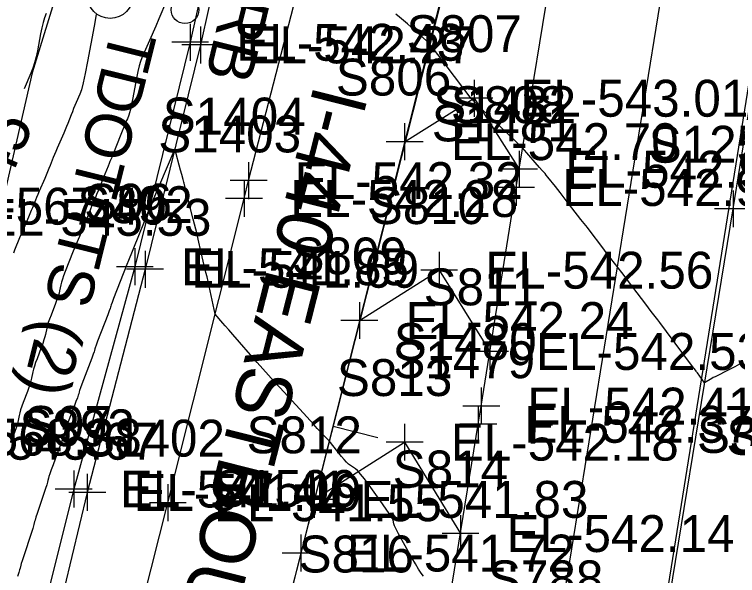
# Model space of a CAD drawing. Extents: x 1724534 to 1727318, y 657156 to 660047.
# Drawn here: x 1725578 to 1725656.3, y 659554.5 to 659615.3 of the extents above; entities that cross this region are included whole.
import ezdxf

# ---------------------------------------------------------------- set-up
doc = ezdxf.new("R2010")
doc.units = 0
for name, color, linetype in [('SURVEY - CENTERLINE - Preliminary', 7, 'Continuous'), ('SURVEY - CENTERLINE - Preliminary Text', 7, 'Continuous'), ('SURVEY - CONTOURS - Index with Text', 7, 'Continuous'), ('SURVEY - CONTOURS - Intermediate with optional Text', 7, 'Continuous'), ('SURVEY - DRAINAGE - Area Shapes', 7, 'Continuous'), ('SURVEY - DTM - Breaklines', 7, 'Continuous'), ('SURVEY - DTM - Breaklines - Points - Elevations', 7, 'Continuous'), ('SURVEY - DTM - Breaklines - Points - Locators', 7, 'Continuous'), ('SURVEY - DTM - Breaklines - Points - Numbers', 7, 'Continuous'), ('SURVEY - NON-TRANSPORTATION - Features - Points - Elevations', 7, 'Continuous'), ('SURVEY - TRAFFIC CONTROL - Pavement Marking - Points - Elevations', 7, 'Continuous'), ('SURVEY - TRAFFIC CONTROL - Pavement Marking - Points - Locators', 7, 'Continuous'), ('SURVEY - TRAFFIC CONTROL - Pavement Marking - Points - Numbers', 7, 'Continuous'), ('SURVEY - TRAFFIC CONTROL - Pavement Marking with Text', 7, 'Continuous'), ('SURVEY - TRANSPORTATION - Features', 7, 'Continuous'), ('SURVEY - TRANSPORTATION - Features - Points - Elevations', 7, 'Continuous'), ('SURVEY - TRANSPORTATION - Features - Points - Locators', 7, 'Continuous'), ('SURVEY - TRANSPORTATION - Features - Points - Numbers', 7, 'Continuous'), ('SURVEY - TRANSPORTATION - Features Text', 7, 'Continuous'), ('SURVEY - TRANSPORTATION - Roads', 7, 'Continuous'), ('SURVEY - TRANSPORTATION - Roads - Points - Elevations', 7, 'Continuous'), ('SURVEY - TRANSPORTATION - Roads - Points - Locators', 7, 'Continuous'), ('SURVEY - TRANSPORTATION - Roads - Points - Numbers', 7, 'Continuous'), ('SURVEY - TRANSPORTATION - Roads Text', 7, 'Continuous'), ('SURVEY - UTILITIES - Electric (Lighting) with Text', 7, 'Continuous'), ('SURVEY - UTILITIES - Fiber Optic Cable (Underground) with Text', 7, 'Continuous'), ('SURVEY - UTILITIES - Poles and Miscellaneous with Text', 7, 'Continuous')]:
    doc.layers.add(name, color=color, linetype=linetype)

msp = doc.modelspace()

# ---------------------------------------------------------------- linework, layer by layer
at = {"layer": 'SURVEY - CENTERLINE - Preliminary'}
msp.add_line((1725628.749, 659634.745), (1725510.016, 659165.778), dxfattribs=at)
msp.add_line((1725628.749, 659634.745), (1725510.016, 659165.778), dxfattribs=at)
msp.add_line((1725628.749, 659634.745), (1725510.016, 659165.778), dxfattribs=at)
at = {"layer": 'SURVEY - CENTERLINE - Preliminary Text'}
msp.add_line((1725612.522, 659570.651), (1725617.369, 659569.424), dxfattribs=at)
at = {"layer": 'SURVEY - CONTOURS - Index with Text'}
msp.add_lwpolyline([(1725581.44, 659615.386), (1725581.278, 659614.944), (1725581.126, 659614.432), (1725580.983, 659613.849), (1725580.851, 659613.197), (1725580.51, 659611.362), (1725580.37, 659610.695), (1725580.204, 659610.068), (1725580.014, 659609.482), (1725579.799, 659608.938), (1725579.065, 659607.246)], dxfattribs=at)
at = {"layer": 'SURVEY - CONTOURS - Intermediate with optional Text'}
for points in [[(1725594.473, 659616.778), (1725593.644, 659614.818), (1725593.31, 659614.042), (1725591.795, 659610.582), (1725591.659, 659610.216), (1725591.52, 659609.728), (1725591.378, 659609.118), (1725591.233, 659608.387), (1725590.84, 659606.274), (1725590.703, 659605.562), (1725590.587, 659605.011), (1725590.491, 659604.62), (1725590.416, 659604.39), (1725590.242, 659603.991), (1725590.159, 659603.794), (1725590.04, 659603.501), (1725589.691, 659602.629), (1725588.936, 659600.727), (1725588.776, 659600.331), (1725588.651, 659600.025), (1725588.56, 659599.809), (1725588.362, 659599.354), (1725588.271, 659599.141), (1725588.149, 659598.843), (1725587.807, 659597.993), (1725587.078, 659596.163), (1725586.92, 659595.772), (1725586.792, 659595.461), (1725586.694, 659595.23), (1725586.471, 659594.72), (1725586.373, 659594.492), (1725586.248, 659594.189), (1725585.914, 659593.359), (1725585.211, 659591.601), (1725585.054, 659591.215), (1725584.923, 659590.9), (1725584.818, 659590.653), (1725584.374, 659589.636), (1725583.508, 659587.417), (1725583.34, 659586.974), (1725583.206, 659586.589), (1725583.107, 659586.262), (1725583.041, 659585.994), (1725582.91, 659585.356), (1725582.845, 659585.089), (1725582.748, 659584.766), (1725582.617, 659584.386), (1725582.454, 659583.95), (1725581.977, 659582.713), (1725581.814, 659582.275), (1725581.682, 659581.891), (1725581.583, 659581.56), (1725581.515, 659581.283), (1725581.378, 659580.613), (1725581.311, 659580.337), (1725581.213, 659580.009), (1725581.085, 659579.63), (1725580.926, 659579.199), (1725580.462, 659577.983), (1725580.303, 659577.552), (1725580.174, 659577.169), (1725580.075, 659576.836), (1725580.006, 659576.552), (1725579.863, 659575.859), (1725579.795, 659575.576), (1725579.698, 659575.245), (1725579.572, 659574.868), (1725579.417, 659574.443), (1725578.965, 659573.247), (1725578.81, 659572.821), (1725578.683, 659572.44), (1725578.585, 659572.105), (1725578.515, 659571.814), (1725578.366, 659571.099), (1725578.297, 659570.81), (1725578.2, 659570.477), (1725578.076, 659570.101), (1725577.925, 659569.682)], [(1725586.882, 659615.305), (1725586.645, 659614.04), (1725585.934, 659610.21), (1725585.682, 659608.911), (1725585.46, 659607.887), (1725585.269, 659607.138), (1725585.107, 659606.664), (1725584.717, 659605.765), (1725584.572, 659605.427), (1725584.429, 659605.088), (1725584.29, 659604.748), (1725584.152, 659604.405), (1725583.79, 659603.491), (1725583.651, 659603.146), (1725583.508, 659602.798), (1725583.36, 659602.446), (1725583.207, 659602.091), (1725582.792, 659601.139), (1725582.64, 659600.787), (1725582.495, 659600.443), (1725582.357, 659600.107), (1725582.225, 659599.78), (1725581.882, 659598.919), (1725581.749, 659598.589), (1725581.607, 659598.246), (1725581.457, 659597.89), (1725581.297, 659597.52), (1725580.7, 659596.148), (1725580.552, 659595.799), (1725580.414, 659595.469), (1725580.288, 659595.157), (1725579.966, 659594.349), (1725579.838, 659594.034), (1725579.698, 659593.696), (1725579.544, 659593.335), (1725578.915, 659591.894), (1725578.562, 659591.085), (1725578.038, 659589.743), (1725577.929, 659589.438)], [(1725656.549, 659577.375), (1725656.023, 659577.1), (1725655.58, 659576.871), (1725655.222, 659576.688), (1725654.946, 659576.551), (1725654.323, 659576.248), (1725654.099, 659576.137), (1725653.891, 659576.03), (1725653.7, 659575.927), (1725653.527, 659575.829), (1725652.757, 659575.383), (1725651.976, 659576.44), (1725651.908, 659576.535), (1725651.893, 659576.564), (1725651.835, 659576.638), (1725651.757, 659576.733), (1725651.439, 659577.154), (1725648.634, 659580.917), (1725647.902, 659581.891), (1725647.674, 659582.19), (1725646.977, 659583.096), (1725646.387, 659583.876), (1725644.523, 659586.359), (1725644.142, 659586.861), (1725643.779, 659587.336), (1725642.209, 659589.363), (1725641.61, 659590.144), (1725640.365, 659591.789), (1725640.06, 659592.187), (1725639.364, 659593.083), (1725637.752, 659595.148), (1725637.437, 659595.557), (1725637.108, 659595.988), (1725636.592, 659596.649), (1725635.787, 659597.672), (1725635.616, 659597.884), (1725635.48, 659598.047), (1725635.38, 659598.161), (1725635.16, 659598.399), (1725634.889, 659598.702), (1725634.409, 659599.253), (1725633.04, 659600.827), (1725629.195, 659604.496), (1725628.716, 659604.957), (1725628.38, 659605.286), (1725628.185, 659605.482), (1725627.745, 659605.945), (1725627.663, 659606.029), (1725627.608, 659606.083), (1725627.58, 659606.105), (1725627.543, 659606.124), (1725627.525, 659606.138), (1725627.5, 659606.165), (1725627.466, 659606.205), (1725622.953, 659612.149), (1725620.991, 659613.91), (1725620.571, 659614.281), (1725620.152, 659614.641), (1725619.733, 659614.99), (1725619.315, 659615.327)], [(1725622.31, 659554.396), (1725622.066, 659554.733), (1725621.775, 659555.18), (1725621.438, 659555.74), (1725621.055, 659556.41), (1725619.97, 659558.348), (1725619.61, 659559.002), (1725619.345, 659559.509), (1725619.175, 659559.87), (1725619.099, 659560.084), (1725619.022, 659560.462), (1725618.928, 659560.681), (1725618.706, 659561.053), (1725618.354, 659561.58), (1725617.873, 659562.261), (1725616.417, 659564.281), (1725615.915, 659564.96), (1725615.501, 659565.482), (1725615.174, 659565.847), (1725614.936, 659566.056), (1725614.416, 659566.401), (1725614.209, 659566.56), (1725613.978, 659566.776), (1725613.723, 659567.05), (1725613.444, 659567.381), (1725612.086, 659569.062), (1725610.805, 659570.428), (1725610.429, 659570.837), (1725609.67, 659571.682), (1725608.917, 659572.505), (1725606.758, 659574.853), (1725606.151, 659575.517), (1725605.541, 659576.193), (1725604.928, 659576.882), (1725604.31, 659577.583), (1725601.679, 659580.588), (1725601.218, 659581.11), (1725600.84, 659581.53), (1725600.589, 659581.818), (1725599.743, 659582.803), (1725598.876, 659586.848), (1725598.756, 659587.322), (1725598.598, 659587.949), (1725598.531, 659588.222), (1725598.448, 659588.572), (1725598.237, 659589.499), (1725597.913, 659590.939), (1725597.788, 659591.48), (1725597.658, 659592.025), (1725597.521, 659592.572), (1725597.379, 659593.123), (1725596.859, 659595.101), (1725596.668, 659595.844), (1725596.611, 659596.081), (1725596.387, 659597.024), (1725596.367, 659597.104), (1725596.291, 659597.396), (1725596.137, 659597.96), (1725596.015, 659598.405), (1725595.375, 659600.736), (1725593.601, 659596.567), (1725592.599, 659594.22), (1725592.047, 659592.835), (1725590.302, 659588.464), (1725590.258, 659588.356), (1725590.186, 659588.187), (1725588.751, 659584.509), (1725588.586, 659584.079), (1725588.484, 659583.803), (1725588.444, 659583.681), (1725588.419, 659583.558), (1725588.379, 659583.437), (1725588.28, 659583.166), (1725588.121, 659582.746), (1725587.018, 659579.881), (1725586.857, 659579.455), (1725586.756, 659579.174), (1725586.714, 659579.039), (1725586.68, 659578.875), (1725586.638, 659578.742), (1725586.54, 659578.466), (1725586.384, 659578.048), (1725585.315, 659575.237), (1725585.158, 659574.814), (1725585.058, 659574.529), (1725585.014, 659574.384), (1725584.972, 659574.181), (1725584.929, 659574.037), (1725584.831, 659573.757), (1725584.679, 659573.341), (1725584.472, 659572.789), (1725583.847, 659571.136), (1725583.64, 659570.582), (1725583.487, 659570.161), (1725583.387, 659569.873), (1725583.342, 659569.717), (1725583.292, 659569.479), (1725583.247, 659569.325), (1725583.151, 659569.041), (1725583.002, 659568.628), (1725582.801, 659568.085), (1725582.195, 659566.466), (1725581.994, 659565.922), (1725581.844, 659565.504), (1725581.745, 659565.213), (1725581.698, 659565.047), (1725581.641, 659564.775), (1725581.598, 659564.61), (1725581.509, 659564.32), (1725581.376, 659563.904), (1725581.197, 659563.363), (1725580.483, 659561.208), (1725580.347, 659560.789), (1725580.255, 659560.493), (1725580.205, 659560.321), (1725580.131, 659560.026), (1725580.081, 659559.855), (1725579.99, 659559.563), (1725579.857, 659559.15), (1725578.982, 659556.497), (1725578.848, 659556.08), (1725578.755, 659555.781), (1725578.703, 659555.6), (1725578.621, 659555.275), (1725578.57, 659555.095), (1725578.479, 659554.8), (1725578.347, 659554.389)]]:
    msp.add_lwpolyline(points, dxfattribs=at)
at = {"layer": 'SURVEY - DRAINAGE - Area Shapes'}
msp.add_lwpolyline([(1725457.865, 659006.777), (1725413.857, 659016.262), (1725297.605, 659050.843), (1725314.042, 659296.608), (1725386.76, 659493.901), (1725483.401, 659755.229), (1725623.949, 659732.704), (1725676.22, 659724.326), (1725634.82, 659466.017), (1725543.324, 659353.721), (1725499.683, 659185.923), (1725479.088, 659106.738)], close=True, dxfattribs=at)
at = {"layer": 'SURVEY - DTM - Breaklines'}
msp.add_lwpolyline([(1725602.477, 659636.589), (1725597.046, 659612.281), (1725591.056, 659587.95), (1725584.432, 659563.857), (1725578.377, 659539.615), (1725572.193, 659515.421), (1725566.455, 659491.037), (1725562.449, 659475.306), (1725561.076, 659469.841), (1725554.596, 659445.712), (1725548.416, 659421.487), (1725542.14, 659397.279), (1725535.913, 659373.067), (1725529.984, 659349.877), (1725523.806, 659325.59), (1725517.787, 659301.313), (1725511.183, 659275.168), (1725504.884, 659250.966), (1725498.725, 659226.793)], dxfattribs=at)
at = {"layer": 'SURVEY - DTM - Breaklines - Points - Locators'}
for p, q in [((1725597.046, 659614.281), (1725597.046, 659610.281)), ((1725599.046, 659612.281), (1725595.046, 659612.281)), ((1725591.056, 659589.95), (1725591.056, 659585.95)), ((1725593.056, 659587.95), (1725589.056, 659587.95)), ((1725584.432, 659565.857), (1725584.432, 659561.857)), ((1725586.432, 659563.857), (1725582.432, 659563.857))]:
    msp.add_line(p, q, dxfattribs=at)
at = {"layer": 'SURVEY - TRAFFIC CONTROL - Pavement Marking - Points - Locators'}
for p, q in [((1725627.806, 659608.215), (1725627.806, 659604.215)), ((1725629.806, 659606.215), (1725625.806, 659606.215)), ((1725620.269, 659603.507), (1725620.269, 659599.507)), ((1725622.269, 659601.507), (1725618.269, 659601.507)), ((1725632.661, 659600.515), (1725632.661, 659596.515)), ((1725634.661, 659598.515), (1725630.661, 659598.515)), ((1725624.011, 659589.575), (1725624.011, 659585.575)), ((1725626.011, 659587.575), (1725622.011, 659587.575)), ((1725615.379, 659584.118), (1725615.379, 659580.118)), ((1725617.379, 659582.118), (1725613.379, 659582.118)), ((1725629.508, 659580.767), (1725629.508, 659576.767)), ((1725631.508, 659578.767), (1725627.508, 659578.767)), ((1725620.274, 659570.935), (1725620.274, 659566.935)), ((1725622.274, 659568.935), (1725618.274, 659568.935)), ((1725610.489, 659564.728), (1725610.489, 659560.728)), ((1725612.489, 659562.728), (1725608.489, 659562.728)), ((1725626.318, 659561.026), (1725626.318, 659557.026)), ((1725628.318, 659559.026), (1725624.318, 659559.026))]:
    msp.add_line(p, q, dxfattribs=at)
at = {"layer": 'SURVEY - TRAFFIC CONTROL - Pavement Marking with Text'}
for points in [[(1725677.077, 659796.306), (1725674.763, 659781.986), (1725662.242, 659705.025), (1725649.129, 659624.102), (1725636.683, 659547.114), (1725636.368, 659545.139), (1725624.177, 659468.103), (1725623.248, 659462.175), (1725617.375, 659424.632), (1725617.069, 659422.656), (1725605.507, 659345.515), (1725605.215, 659343.536), (1725602.951, 659328.104)], [(1725620.269, 659601.507), (1725627.806, 659606.215), (1725632.661, 659598.515)], [(1725615.379, 659582.118), (1725624.011, 659587.575), (1725629.508, 659578.767)], [(1725610.489, 659562.728), (1725620.274, 659568.935), (1725626.318, 659559.026)]]:
    msp.add_lwpolyline(points, dxfattribs=at)
at = {"layer": 'SURVEY - TRANSPORTATION - Features'}
msp.add_lwpolyline([(1725603.581, 659636.317), (1725598.147, 659611.998), (1725592.159, 659587.674), (1725585.904, 659563.486), (1725580.094, 659539.18), (1725573.908, 659514.982), (1725567.671, 659490.732), (1725563.666, 659475.001), (1725562.294, 659469.536), (1725556.226, 659445.299), (1725550.205, 659421.034), (1725543.929, 659396.827), (1725537.702, 659372.615), (1725531.77, 659349.415), (1725525.595, 659325.139), (1725519.577, 659300.865), (1725512.973, 659274.714), (1725506.673, 659250.514), (1725500.512, 659226.334)], dxfattribs=at)
at = {"layer": 'SURVEY - TRANSPORTATION - Features - Points - Locators'}
for p, q in [((1725598.147, 659613.998), (1725598.147, 659609.998)), ((1725600.147, 659611.998), (1725596.147, 659611.998)), ((1725592.159, 659589.674), (1725592.159, 659585.674)), ((1725594.159, 659587.674), (1725590.159, 659587.674)), ((1725585.904, 659565.486), (1725585.904, 659561.486)), ((1725587.904, 659563.486), (1725583.904, 659563.486))]:
    msp.add_line(p, q, dxfattribs=at)
at = {"layer": 'SURVEY - TRANSPORTATION - Roads'}
for points in [[(1725614.209, 659327.48), (1725617.731, 659353.241), (1725618.016, 659355.22), (1725622.921, 659386.843), (1725624.432, 659396.727), (1725627.753, 659418.475), (1725628.057, 659420.452), (1725635.106, 659465.907), (1725635.414, 659467.883), (1725643.908, 659521.207), (1725646.487, 659536.996), (1725655.836, 659594.229), (1725667.285, 659665.297), (1725672.1, 659694.897), (1725680.449, 659746.206), (1725687.947, 659792.609)], [(1725590.712, 659328.916), (1725598.166, 659381.246), (1725598.45, 659383.225), (1725602.437, 659408.918), (1725603.053, 659412.87), (1725607.12, 659438.551), (1725610.58, 659460.277), (1725610.891, 659462.253), (1725615.777, 659493.878), (1725619.05, 659513.608), (1725619.366, 659515.583), (1725622.791, 659537.313), (1725623.106, 659539.288), (1725628.245, 659570.869), (1725628.563, 659572.843), (1725632.342, 659596.54), (1725632.661, 659598.515), (1725636.547, 659622.193)], [(1725509.717, 659226.971), (1725517.054, 659256.051), (1725522.463, 659277.37), (1725530.246, 659308.405), (1725536.116, 659331.674), (1725536.614, 659333.611), (1725542.122, 659354.908), (1725554.364, 659403.386), (1725567.129, 659453.798), (1725567.617, 659455.737), (1725576.381, 659490.656), (1725576.873, 659492.594), (1725587.785, 659535.219), (1725588.276, 659537.157), (1725594.628, 659562.367), (1725602.882, 659595.344), (1725603.37, 659597.283), (1725609.346, 659620.521)], [(1725624.67, 659618.957), (1725609.021, 659556.912), (1725594.317, 659498.747), (1725580.515, 659444.472), (1725570.134, 659403.773), (1725561.33, 659368.865), (1725557.927, 659355.285), (1725547.165, 659312.624), (1725545.206, 659304.869), (1725533.446, 659258.339), (1725527.51, 659235.091)]]:
    msp.add_lwpolyline(points, dxfattribs=at)
at = {"layer": 'SURVEY - TRANSPORTATION - Roads - Points - Locators'}
for p, q in [((1725632.661, 659600.515), (1725632.661, 659596.515)), ((1725603.37, 659599.283), (1725603.37, 659595.283)), ((1725634.661, 659598.515), (1725630.661, 659598.515)), ((1725632.342, 659598.54), (1725632.342, 659594.54)), ((1725605.37, 659597.283), (1725601.37, 659597.283)), ((1725602.882, 659597.344), (1725602.882, 659593.344)), ((1725634.342, 659596.54), (1725630.342, 659596.54)), ((1725655.836, 659596.229), (1725655.836, 659592.229)), ((1725604.882, 659595.344), (1725600.882, 659595.344)), ((1725657.836, 659594.229), (1725653.836, 659594.229)), ((1725628.563, 659574.843), (1725628.563, 659570.843)), ((1725630.563, 659572.843), (1725626.563, 659572.843)), ((1725628.245, 659572.869), (1725628.245, 659568.869)), ((1725630.245, 659570.869), (1725626.245, 659570.869)), ((1725594.628, 659564.367), (1725594.628, 659560.367)), ((1725596.628, 659562.367), (1725592.628, 659562.367)), ((1725609.021, 659558.912), (1725609.021, 659554.912)), ((1725611.021, 659556.912), (1725607.021, 659556.912))]:
    msp.add_line(p, q, dxfattribs=at)
at = {"layer": 'SURVEY - UTILITIES - Electric (Lighting) with Text'}
for centre, radius in [((1725588.381, 659617.37), 2.5), ((1725596.482, 659615.808), 1.5)]:
    msp.add_circle(centre, radius, dxfattribs=at)
at = {"layer": 'SURVEY - UTILITIES - Fiber Optic Cable (Underground) with Text'}
msp.add_lwpolyline([(1725620.739, 659775.717), (1725611.515, 659729.876), (1725595.678, 659670.817), (1725588.852, 659637.987), (1725579.945, 659608.985), (1725572.052, 659574.699), (1725561.954, 659530.586), (1725538.949, 659448.715), (1725526.808, 659392.271), (1725505.744, 659313.434), (1725493.556, 659248.407)], dxfattribs=at)

# ---------------------------------------------------------------- texts
at = {"layer": 'SURVEY - CONTOURS - Index with Text'}
msp.add_text('545', height=5, rotation=66.79658, dxfattribs=at).set_placement((1725575.778, 659593.173))
at = {"layer": 'SURVEY - DTM - Breaklines - Points - Elevations'}
for s, p in [('EL-542.43', (1725602.046, 659610.281)), ('EL-567.40', (1725569.828, 659592.513)), ('EL-541.85', (1725596.056, 659585.95)), ('EL-568.38', (1725567.116, 659567.482)), ('EL-541.41', (1725589.432, 659561.857))]:
    msp.add_text(s, height=4, dxfattribs=at).set_placement(p)
at = {"layer": 'SURVEY - DTM - Breaklines - Points - Numbers'}
for s, p in [('S96', (1725585.562, 659592.95)), ('S97', (1725579.048, 659568.857)), ('S78', (1725655.118, 659567.561))]:
    msp.add_text(s, height=4, dxfattribs=at).set_placement(p)
at = {"layer": 'SURVEY - NON-TRANSPORTATION - Features - Points - Elevations'}
for s, p in [('EL-545.53', (1725574.664, 659591.303)), ('EL-545.67', (1725568.899, 659567.033))]:
    msp.add_text(s, height=4, dxfattribs=at).set_placement(p)
at = {"layer": 'SURVEY - TRAFFIC CONTROL - Pavement Marking - Points - Elevations'}
for s, p in [('EL-543.01', (1725632.806, 659604.215)), ('EL-542.70', (1725625.269, 659599.507)), ('EL-542.95', (1725637.661, 659596.515)), ('EL-542.56', (1725629.011, 659585.575)), ('EL-542.24', (1725620.379, 659580.118)), ('EL-542.53', (1725634.508, 659576.767)), ('EL-542.18', (1725625.274, 659566.935)), ('EL-541.83', (1725615.489, 659560.728)), ('EL-542.14', (1725631.318, 659557.026))]:
    msp.add_text(s, height=4, dxfattribs=at).set_placement(p)
at = {"layer": 'SURVEY - TRAFFIC CONTROL - Pavement Marking - Points - Numbers'}
for s, p in [('S807', (1725620.47, 659611.215)), ('S806', (1725612.823, 659606.507)), ('S808', (1725625.278, 659603.515)), ('S810', (1725616.502, 659592.575)), ('S809', (1725608.027, 659587.118)), ('S811', (1725622.33, 659583.767)), ('S813', (1725612.938, 659573.935)), ('S812', (1725603.153, 659567.728)), ('S814', (1725618.982, 659564.026)), ('S816', (1725608.79, 659554.808)), ('S788', (1725629.3, 659552.114))]:
    msp.add_text(s, height=4, dxfattribs=at).set_placement(p)
at = {"layer": 'SURVEY - TRANSPORTATION - Features - Points - Elevations'}
for s, p in [('EL-542.27', (1725603.147, 659609.998)), ('EL-541.69', (1725597.159, 659585.674)), ('EL-541.19', (1725590.904, 659561.486))]:
    msp.add_text(s, height=4, dxfattribs=at).set_placement(p)
at = {"layer": 'SURVEY - TRANSPORTATION - Features - Points - Numbers'}
for s, p in [('S392', (1725584.823, 659592.674)), ('S393', (1725578.568, 659568.486)), ('S374', (1725651.929, 659567.771))]:
    msp.add_text(s, height=4, dxfattribs=at).set_placement(p)
at = {"layer": 'SURVEY - TRANSPORTATION - Features Text'}
msp.add_text('CURB', height=5, rotation=256.17012, dxfattribs=at).set_placement((1725603.162, 659627.074))
at = {"layer": 'SURVEY - TRANSPORTATION - Roads - Points - Elevations'}
for s, p in [('EL-542.95', (1725637.661, 659596.515)), ('EL-542.32', (1725608.37, 659595.283)), ('EL-542.90', (1725637.342, 659594.54)), ('EL-542.28', (1725607.882, 659593.344)), ('EL-542.41', (1725633.563, 659570.843)), ('EL-542.37', (1725633.245, 659568.869)), ('EL-541.55', (1725599.628, 659560.367)), ('EL-541.72', (1725614.021, 659554.912))]:
    msp.add_text(s, height=4, dxfattribs=at).set_placement(p)
at = {"layer": 'SURVEY - TRANSPORTATION - Roads - Points - Numbers'}
for s, p in [('S1482', (1725623.373, 659603.515)), ('S1404', (1725594.082, 659602.283)), ('S1481', (1725623.212, 659601.54)), ('S1403', (1725593.594, 659600.344)), ('S1251', (1725646.706, 659599.229)), ('S1480', (1725619.102, 659577.843)), ('S1479', (1725618.942, 659575.869)), ('S1402', (1725585.34, 659567.367)), ('S1506', (1725599.623, 659561.912))]:
    msp.add_text(s, height=4, dxfattribs=at).set_placement(p)
at = {"layer": 'SURVEY - TRANSPORTATION - Roads Text'}
msp.add_text('I-440 EASTBOUND EXIT RAMP (ASP)', height=6, rotation=255.74674, dxfattribs=at).set_placement((1725610.504, 659607.819))
at = {"layer": 'SURVEY - UTILITIES - Poles and Miscellaneous with Text'}
msp.add_text('TDOT ITS (2)', height=5, rotation=256.04999, dxfattribs=at).set_placement((1725588.552, 659613.936))

doc.saveas('drawing.dxf')
